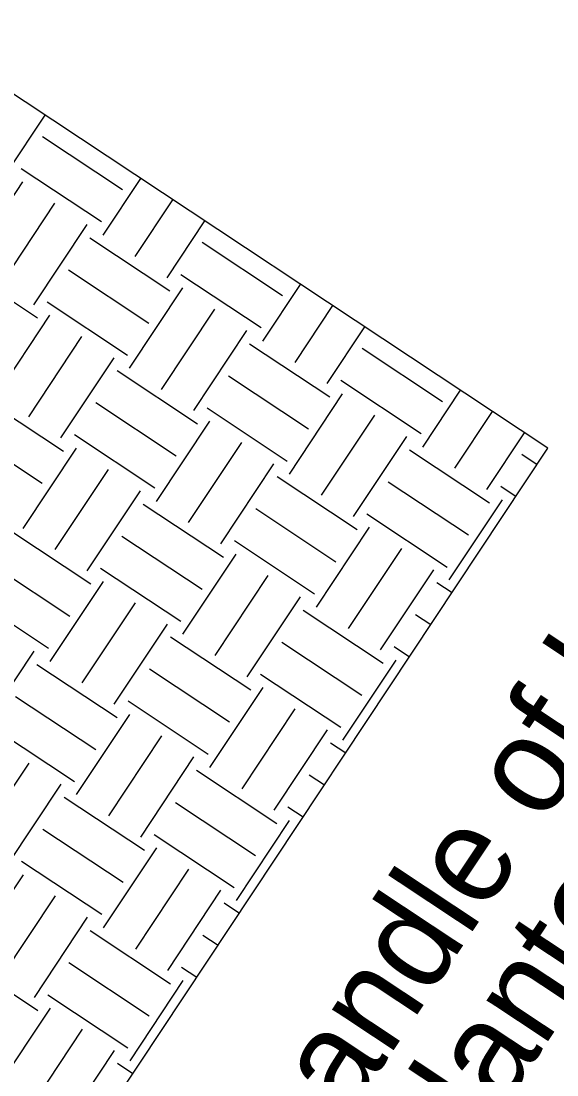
# Model space of a CAD drawing. Extents: x 561231 to 564240, y 590260 to 602519.
# Drawn here: x 563636.97 to 563657.68, y 590692.34 to 590733.11 of the extents above; entities that cross this region are included whole.
import ezdxf

# ---------------------------------------------------------------- set-up
doc = ezdxf.new("R2010")
doc.units = 0
doc.layers.add('Old_Level_1', color=7, linetype='Continuous')

msp = doc.modelspace()

# ---------------------------------------------------------------- linework, layer by layer
at = {"layer": 'Old_Level_1'}
for p, q in [((563657.335, 590716.579), (563632.417, 590733.108)), ((563636.44, 590727.279), (563637.895, 590729.474)), ((563637.793, 590728.647), (563640.893, 590726.59)), ((563636.97, 590727.406), (563640.071, 590725.35)), ((563634.981, 590723.782), (563637.038, 590726.882)), ((563640.138, 590724.825), (563641.594, 590727.02)), ((563636.221, 590722.959), (563638.278, 590726.06)), ((563641.379, 590724.003), (563642.834, 590726.198)), ((563637.461, 590722.136), (563639.518, 590725.237)), ((563642.619, 590723.18), (563644.074, 590725.375)), ((563639.622, 590724.721), (563642.723, 590722.665)), ((563643.972, 590724.548), (563647.073, 590722.491)), ((563634.503, 590723.686), (563637.603, 590721.629)), ((563638.8, 590723.481), (563641.901, 590721.424)), ((563643.149, 590723.307), (563646.25, 590721.251)), ((563641.16, 590719.683), (563643.217, 590722.783)), ((563646.318, 590720.727), (563647.773, 590722.921)), ((563637.978, 590722.241), (563641.078, 590720.184)), ((563642.4, 590718.86), (563644.457, 590721.961)), ((563647.558, 590719.904), (563649.013, 590722.098)), ((563636.025, 590718.625), (563638.082, 590721.725)), ((563643.641, 590718.038), (563645.697, 590721.138)), ((563648.798, 590719.081), (563650.254, 590721.276)), ((563637.265, 590717.802), (563639.322, 590720.902)), ((563645.802, 590720.623), (563648.902, 590718.566)), ((563650.152, 590720.449), (563653.252, 590718.393)), ((563638.505, 590716.979), (563640.562, 590720.08)), ((563640.682, 590719.587), (563643.782, 590717.531)), ((563644.979, 590719.382), (563648.08, 590717.326)), ((563649.329, 590719.209), (563652.429, 590717.153)), ((563647.34, 590715.584), (563649.396, 590718.685)), ((563652.497, 590716.628), (563653.952, 590718.822)), ((563635.509, 590718.521), (563638.61, 590716.464)), ((563639.859, 590718.347), (563642.959, 590716.291)), ((563644.157, 590718.142), (563647.257, 590716.086)), ((563648.58, 590714.761), (563650.636, 590717.862)), ((563653.737, 590715.805), (563655.192, 590718)), ((563642.204, 590714.526), (563644.261, 590717.626)), ((563634.687, 590717.28), (563637.787, 590715.224)), ((563639.037, 590717.107), (563642.137, 590715.051)), ((563649.82, 590713.939), (563651.876, 590717.04)), ((563654.977, 590714.983), (563656.433, 590717.177)), ((563632.887, 590679.722), (563657.335, 590716.579)), ((563637.047, 590713.482), (563639.104, 590716.583)), ((563643.444, 590713.703), (563645.501, 590716.804)), ((563651.981, 590716.524), (563655.081, 590714.467)), ((563656.33, 590716.35), (563656.923, 590715.957)), ((563638.288, 590712.66), (563640.344, 590715.76)), ((563644.684, 590712.881), (563646.741, 590715.981)), ((563646.861, 590715.488), (563649.961, 590713.432)), ((563639.528, 590711.837), (563641.584, 590714.937)), ((563651.158, 590715.283), (563654.259, 590713.227)), ((563655.508, 590715.11), (563656.1, 590714.717)), ((563653.518, 590711.485), (563655.575, 590714.586)), ((563641.689, 590714.422), (563644.789, 590712.365)), ((563646.038, 590714.248), (563649.138, 590712.192)), ((563650.336, 590714.043), (563653.436, 590711.987)), ((563636.569, 590713.386), (563639.669, 590711.33)), ((563648.383, 590710.427), (563650.44, 590713.528)), ((563640.866, 590713.181), (563643.966, 590711.125)), ((563645.215, 590713.008), (563648.316, 590710.951)), ((563643.226, 590709.383), (563645.283, 590712.484)), ((563649.623, 590709.605), (563651.68, 590712.705)), ((563635.746, 590712.146), (563638.846, 590710.09)), ((563640.043, 590711.941), (563643.143, 590709.885)), ((563644.467, 590708.561), (563646.523, 590711.661)), ((563650.863, 590708.782), (563652.92, 590711.882)), ((563638.091, 590708.325), (563640.147, 590711.426)), ((563653.04, 590711.39), (563653.632, 590710.997)), ((563634.923, 590710.906), (563638.024, 590708.849)), ((563645.707, 590707.738), (563647.763, 590710.838)), ((563639.331, 590707.503), (563641.388, 590710.603)), ((563647.868, 590710.323), (563650.968, 590708.266)), ((563652.217, 590710.15), (563652.809, 590709.757)), ((563640.571, 590706.68), (563642.628, 590709.78)), ((563642.748, 590709.288), (563645.848, 590707.231)), ((563647.045, 590709.083), (563650.145, 590707.026)), ((563651.394, 590708.91), (563651.987, 590708.517)), ((563635.414, 590705.636), (563637.471, 590708.736)), ((563649.405, 590705.285), (563651.462, 590708.385)), ((563637.575, 590708.221), (563640.676, 590706.164)), ((563641.925, 590708.048), (563645.025, 590705.991)), ((563646.222, 590707.843), (563649.323, 590705.786)), ((563644.27, 590704.227), (563646.326, 590707.327)), ((563636.753, 590706.981), (563639.853, 590704.924)), ((563641.102, 590706.807), (563644.203, 590704.751)), ((563645.51, 590703.404), (563647.567, 590706.504)), ((563639.113, 590703.183), (563641.17, 590706.283)), ((563635.93, 590705.741), (563639.031, 590703.684)), ((563646.75, 590702.582), (563648.807, 590705.682)), ((563640.353, 590702.36), (563642.41, 590705.46)), ((563648.927, 590705.189), (563649.519, 590704.796)), ((563635.218, 590701.302), (563637.275, 590704.402)), ((563641.593, 590701.537), (563643.65, 590704.638)), ((563643.754, 590704.122), (563646.855, 590702.066)), ((563648.104, 590703.949), (563648.696, 590703.556)), ((563636.458, 590700.48), (563638.515, 590703.58)), ((563638.634, 590703.087), (563641.735, 590701.03)), ((563642.932, 590702.882), (563646.032, 590700.825)), ((563647.281, 590702.708), (563647.873, 590702.316)), ((563637.812, 590701.847), (563640.912, 590699.79)), ((563645.292, 590699.084), (563647.349, 590702.184)), ((563642.109, 590701.642), (563645.209, 590699.585)), ((563640.157, 590698.026), (563642.214, 590701.126)), ((563636.989, 590700.606), (563640.089, 590698.55)), ((563641.397, 590697.203), (563643.454, 590700.303)), ((563635, 590696.982), (563637.056, 590700.082)), ((563642.637, 590696.38), (563644.694, 590699.481)), ((563636.24, 590696.159), (563638.296, 590699.26)), ((563644.813, 590698.988), (563645.405, 590698.595)), ((563637.48, 590695.337), (563639.537, 590698.437)), ((563639.641, 590697.921), (563642.742, 590695.865)), ((563643.991, 590697.748), (563644.583, 590697.355)), ((563634.521, 590696.886), (563637.621, 590694.829)), ((563638.818, 590696.681), (563641.919, 590694.624)), ((563643.168, 590696.508), (563643.76, 590696.115)), ((563641.179, 590692.883), (563643.235, 590695.984)), ((563637.996, 590695.441), (563641.096, 590693.384)), ((563636.044, 590691.825), (563638.1, 590694.925)), ((563637.284, 590691.002), (563639.341, 590694.103)), ((563638.524, 590690.18), (563640.581, 590693.28)), ((563640.7, 590692.787), (563641.293, 590692.395))]:
    msp.add_line(p, q, dxfattribs=at)

# ---------------------------------------------------------------- texts
for s, p in [(' toward planter, firming ', (563643.698, 590673.076)), ('4. Pull handle of bar ', (563639.712, 590675.72)), (' soil at bottom.', (563647.684, 590670.432))]:
    msp.add_text(s, height=3.72047, rotation=56.4424, dxfattribs=at).set_placement(p)

doc.saveas('drawing.dxf')
